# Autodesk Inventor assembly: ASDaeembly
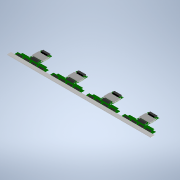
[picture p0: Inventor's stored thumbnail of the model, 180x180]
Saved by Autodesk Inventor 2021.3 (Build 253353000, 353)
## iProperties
Created: 2021-12
Part Number: ASDaeembly
Document SubType Name: Assembly
Designer: kengo
Author: kengo
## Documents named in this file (4)
- C:\Users\kengo\Downloads\aida_kl_frame\AIDA_KL_frame\ASDaeembly.iam
- C:\Users\kengo\Downloads\aida_kl_frame\AIDA_KL_frame\ASD_frame.ipt
- C:\Users\kengo\Downloads\aida_kl_frame\AIDA_KL_frame\ASD_adaptor.ipt
- C:\Users\kengo\Downloads\aida_kl_frame\AIDA_KL_frame\ASDcard.ipt
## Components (9 placed, 3 different names)
1. ASD_frame:1 — メイト:1, 挿入:1, 挿入:2, メイト:2, 挿入:3, メイト:3, メイト:4, メイト:5
2. ASD_adaptor:1 — メイト:1, 挿入:1, メイト:6, メイト:7
3. ASD_adaptor:2 — 挿入:2, メイト:2, メイト:8, メイト:9
4. ASD_adaptor:3 — 挿入:3, メイト:3, メイト:10, メイト:11, メイト:12
5. ASD_adaptor:4 — メイト:4, メイト:5, メイト:13, メイト:14, メイト:15
6. ASDcard:1 — メイト:6, メイト:7
7. ASDcard:2 — メイト:8, メイト:9
8. ASDcard:3 — メイト:10, メイト:11, メイト:12
9. ASDcard:4 — メイト:13, メイト:14, メイト:15
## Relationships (18: Mate 15, Insert 3)
- メイト:1 [Mate]: ASD_frame:1 ↔ ASD_adaptor:1
- 挿入:1 [Insert]: ASD_frame:1 ↔ ASD_adaptor:1
- 挿入:2 [Insert]: ASD_frame:1 ↔ ASD_adaptor:2
- メイト:2 [Mate]: ASD_frame:1 ↔ ASD_adaptor:2
- 挿入:3 [Insert]: ASD_frame:1 ↔ ASD_adaptor:3
- メイト:3 [Mate]: ASD_frame:1 ↔ ASD_adaptor:3
- メイト:4 [Mate]: ASD_frame:1 ↔ ASD_adaptor:4
- メイト:5 [Mate]: ASD_frame:1 ↔ ASD_adaptor:4
- メイト:6 [Mate]: ASD_adaptor:1 ↔ ASDcard:1
- メイト:7 [Mate]: ASD_adaptor:1 ↔ ASDcard:1
- メイト:8 [Mate]: ASD_adaptor:2 ↔ ASDcard:2
- メイト:9 [Mate]: ASD_adaptor:2 ↔ ASDcard:2
- メイト:10 [Mate]: ASD_adaptor:3 ↔ ASDcard:3
- メイト:11 [Mate]: ASD_adaptor:3 ↔ ASDcard:3
- メイト:12 [Mate]: ASD_adaptor:3 ↔ ASDcard:3
- メイト:13 [Mate]: ASD_adaptor:4 ↔ ASDcard:4
- メイト:14 [Mate]: ASD_adaptor:4 ↔ ASDcard:4
- メイト:15 [Mate]: ASD_adaptor:4 ↔ ASDcard:4
